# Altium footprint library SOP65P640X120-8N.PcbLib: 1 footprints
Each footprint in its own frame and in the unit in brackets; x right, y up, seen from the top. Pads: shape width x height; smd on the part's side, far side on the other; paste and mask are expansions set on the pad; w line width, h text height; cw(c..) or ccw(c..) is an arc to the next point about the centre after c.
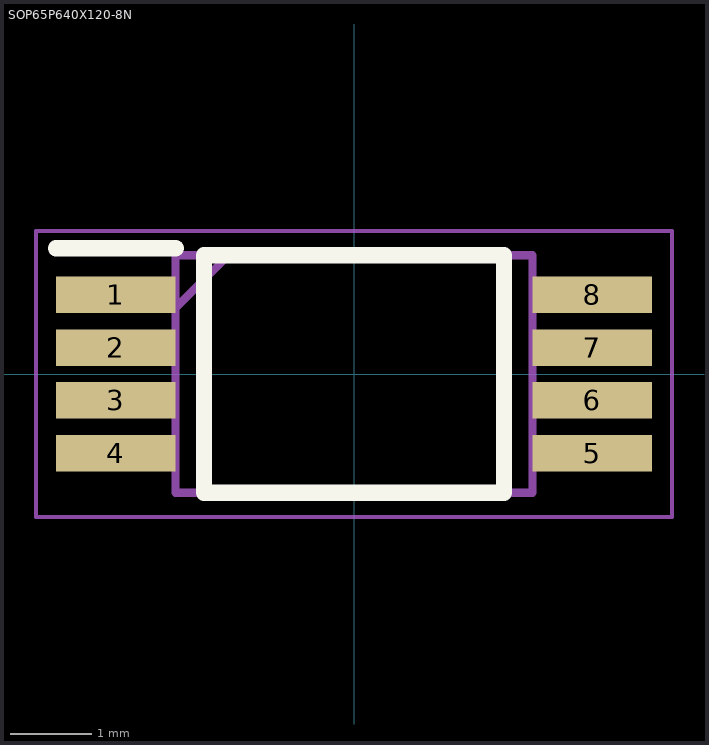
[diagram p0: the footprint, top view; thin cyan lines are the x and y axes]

## SOP65P640X120-8N [mm]
pads (8):
  rect 1.475x0.45 smd: 1(-2.938,0.975) 2(-2.938,0.325) 3(-2.938,-0.325) 4(-2.938,-0.975) 5(2.938,-0.975) 6(2.938,-0.325) 7(2.938,0.325) 8(2.938,0.975)
Top Overlay:
  lines w0.2: -3.675,1.55 -2.2,1.55 ; -1.85,-1.465 1.85,-1.465 1.85,1.465 -1.85,1.465 -1.85,-1.465
Mechanical 15:
  lines w0.1: -2.2,0.815 -1.55,1.465 ; -2.2,-1.465 2.2,-1.465 2.2,1.465 -2.2,1.465 -2.2,-1.465
Mechanical 20:
  lines w0.05: -3.925,-1.765 3.925,-1.765 3.925,1.765 -3.925,1.765 -3.925,-1.765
